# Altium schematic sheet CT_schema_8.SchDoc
size 387 x 278 mm
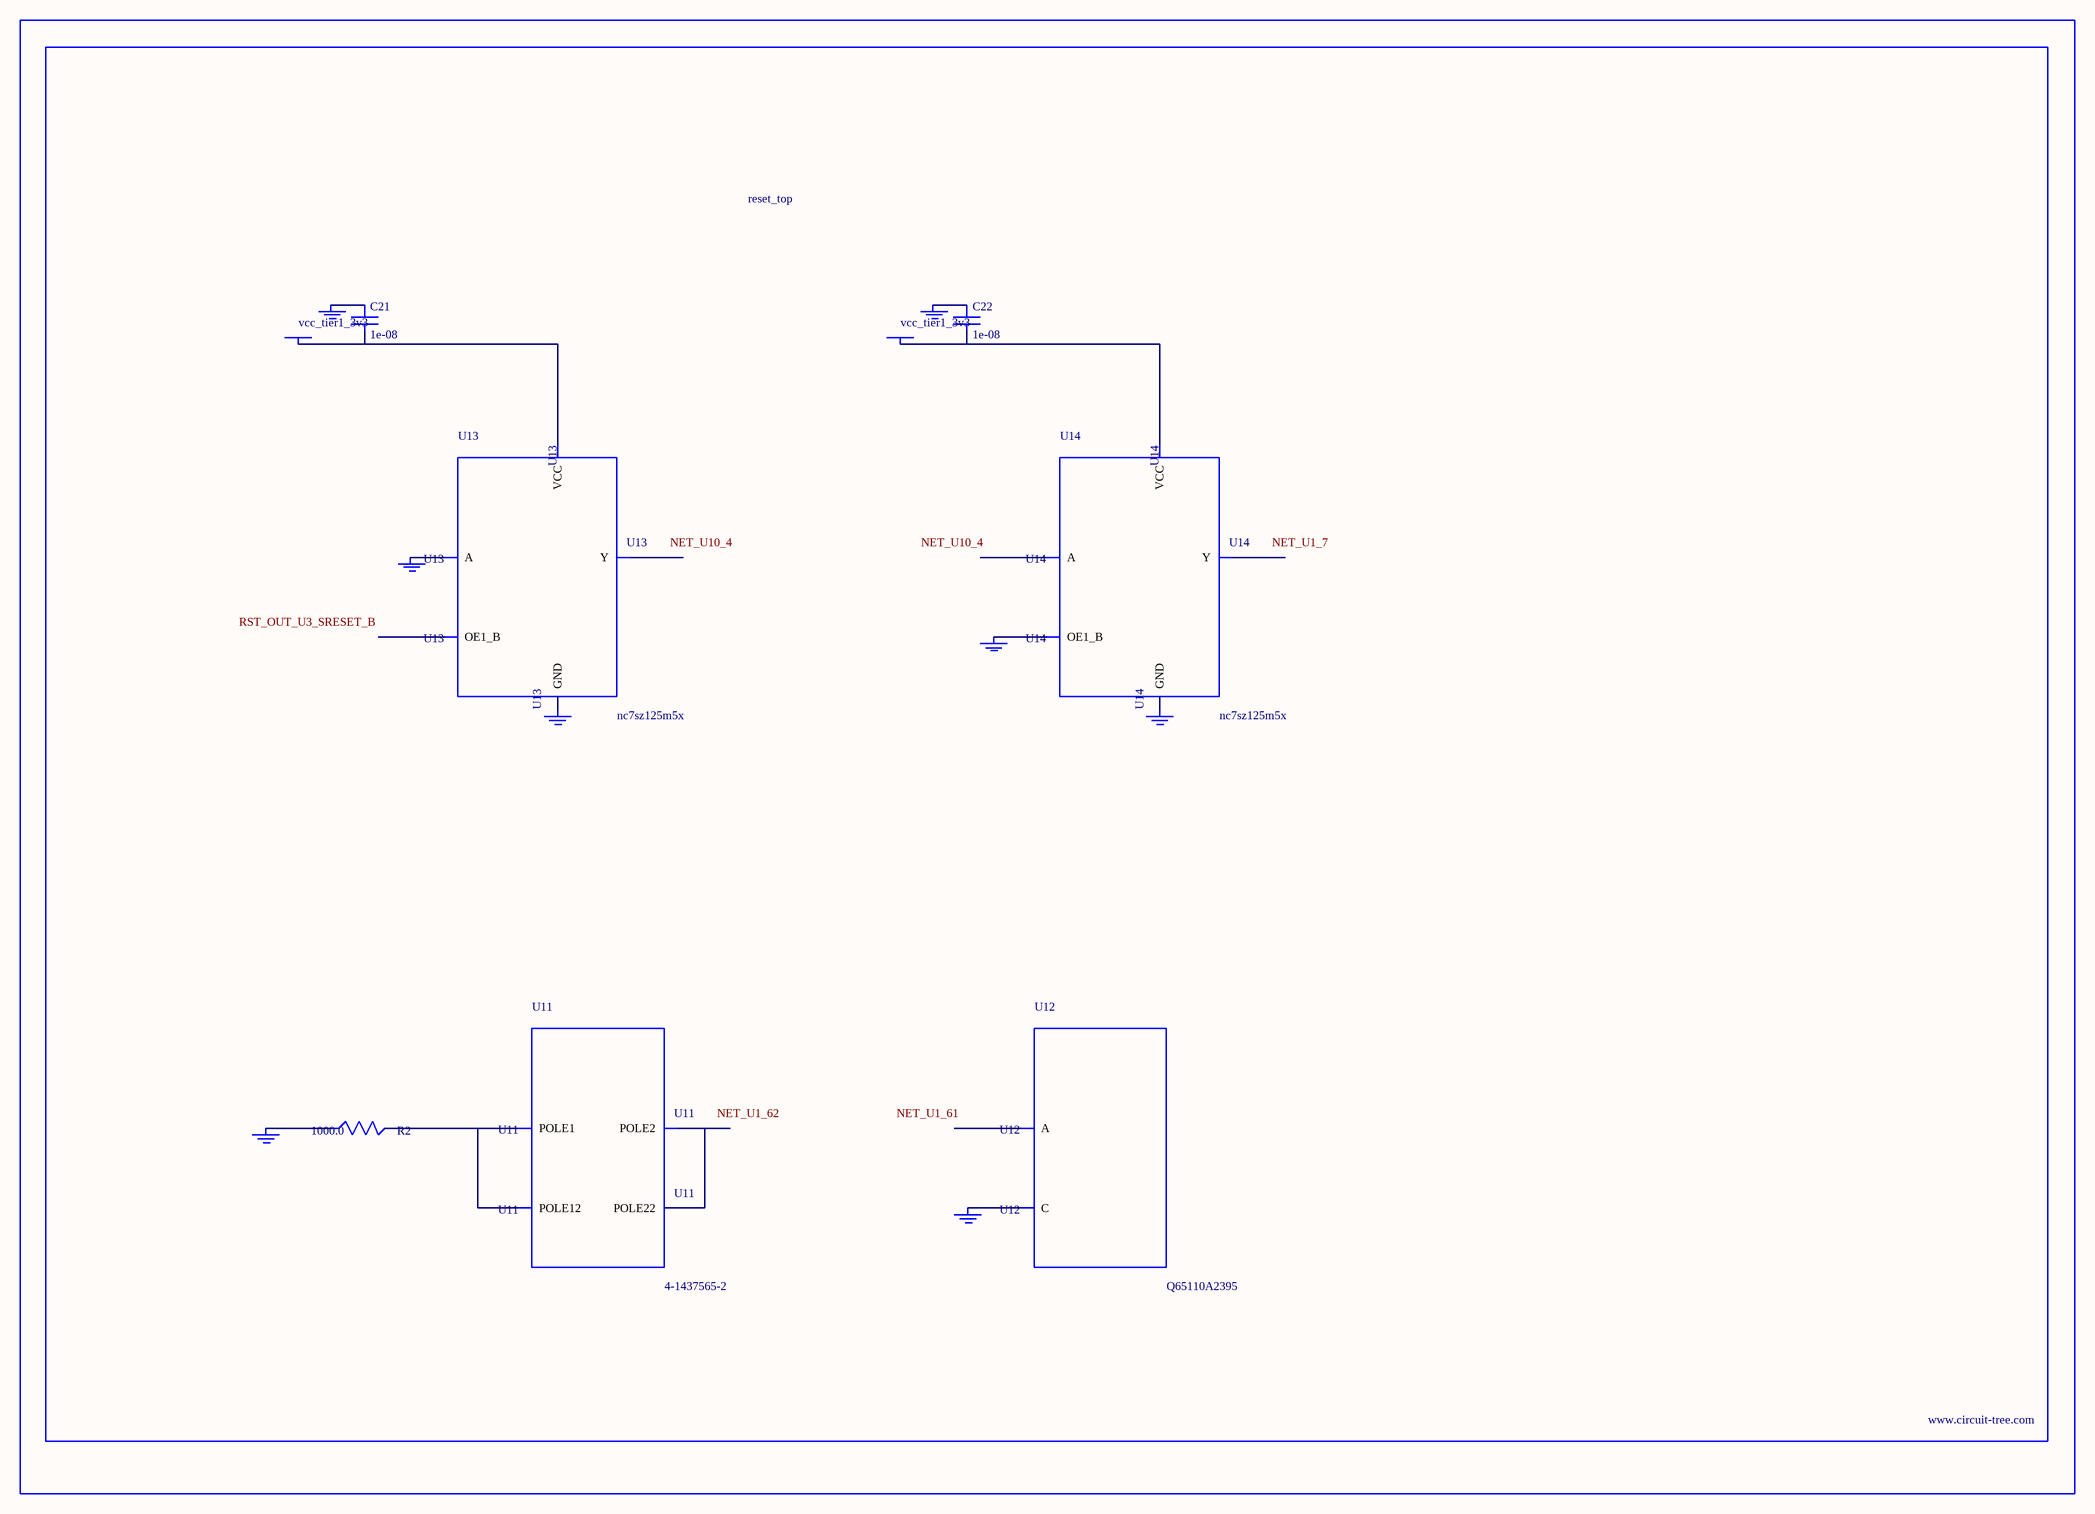
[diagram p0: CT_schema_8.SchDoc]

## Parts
BORDER7  (no value)
C21  1e-08  [C0402]
C22  1e-08  [C0402]
GND_INSTANCE_7_0  (no value)
GND_INSTANCE_7_1  (no value)
GND_INSTANCE_7_2  (no value)
GND_INSTANCE_7_3  (no value)
GND_INSTANCE_7_4  (no value)
GND_INSTANCE_7_5  (no value)
GND_INSTANCE_7_6  (no value)
GND_INSTANCE_7_7  (no value)
POWER_INSTANCE_7_0  vcc_tier1_3v3
POWER_INSTANCE_7_1  vcc_tier1_3v3
R2  1000.0  [R0603]
U11  4-1437565-2  [SW_4-1437565-2]
U12  Q65110A2395  [LGM67K-G1J2-24-Z]
U13  nc7sz125m5x  [NC7SZ125M5X]
U14  nc7sz125m5x  [NC7SZ125M5X]

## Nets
NetC21_1: C21.1 GND_INSTANCE_7_2.0(GND)
NetC21_2: C21.2 POWER_INSTANCE_7_0.0(PWR) U13.5(VCC)
NetC22_1: C22.1 GND_INSTANCE_7_5.0(GND)
NetC22_2: C22.2 POWER_INSTANCE_7_1.0(PWR) U14.5(VCC)
NetGND_INSTANCE_7_0_0: GND_INSTANCE_7_0.0(GND) R2.1
NetGND_INSTANCE_7_1_0: GND_INSTANCE_7_1.0(GND) U12.C
NetGND_INSTANCE_7_3_0: GND_INSTANCE_7_3.0(GND) U13.2(A)
NetGND_INSTANCE_7_4_0: GND_INSTANCE_7_4.0(GND) U13.3(GND)
NetGND_INSTANCE_7_6_0: GND_INSTANCE_7_6.0(GND) U14.1(OE1_B)
NetGND_INSTANCE_7_7_0: GND_INSTANCE_7_7.0(GND) U14.3(GND)
NetR2_2: R2.2 U11.1(POLE1) U11.2(POLE12)
NetU11_3: U11.3(POLE2) U11.4(POLE22)

Not connected (* = marked no-connect by the designer): U12 A; U13 1(OE1_B) 4(Y); U14 2(A) 4(Y)

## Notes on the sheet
- Labels drawn without touching a wire or pin: NET_U1_7, NET_U1_61, NET_U1_62, NET_U10_4, RST_OUT_U3_SRESET_B

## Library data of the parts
BORDER7 = BORDER_PAGE7
C21 C22 = C0402C103K3RAC
GND_INSTANCE_7_0-GND_INSTANCE_7_7 = GND
POWER_INSTANCE_7_0 POWER_INSTANCE_7_1 = PWR
R2 = RC0603JR-071KL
